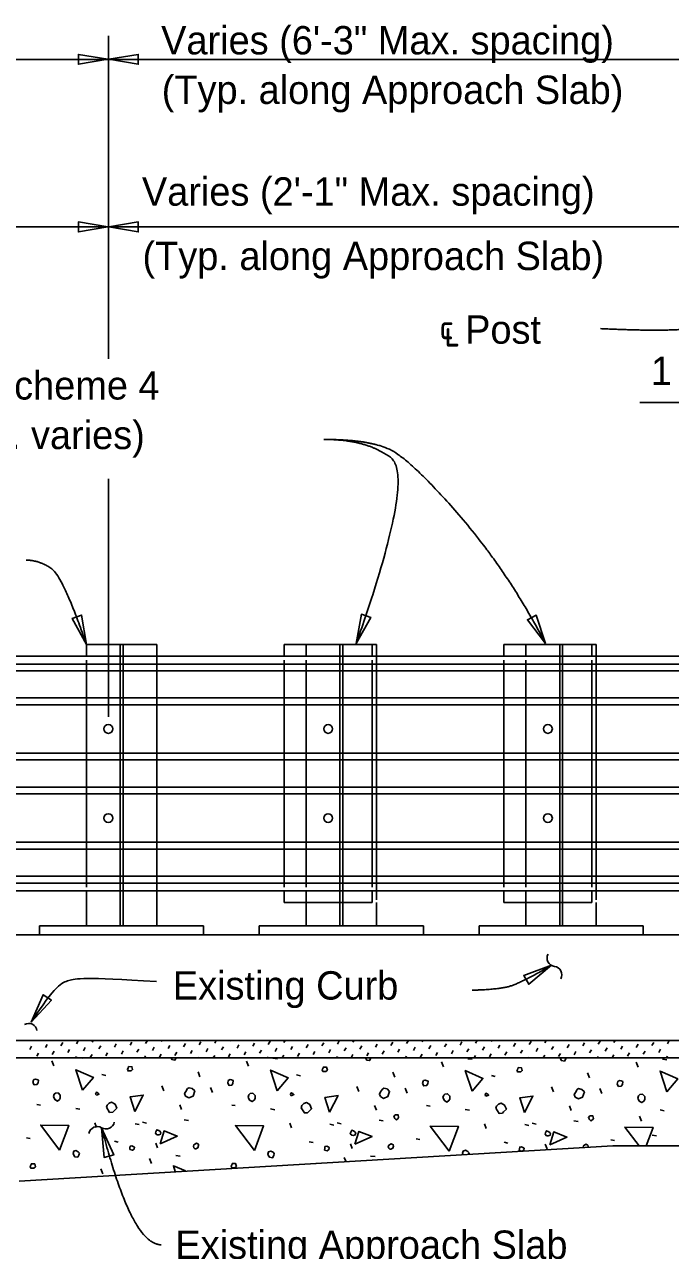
# Model space of a CAD drawing. Extents: x 0 to 41.1, y 0 to 25.9.
# Drawn here: x 8 to 12.6, y 5.22 to 13.93 of the extents above; entities that cross this region are included whole.
import ezdxf

# ---------------------------------------------------------------- set-up
doc = ezdxf.new("R2010")
doc.units = 0
for name, color, linetype in [('Dimension', 7, 'Continuous'), ('ExistSuperStruct', 7, 'Continuous'), ('Miscellaneous', 7, 'Continuous'), ('SteelMisc', 7, 'Continuous'), ('SteelMisc_h', 7, 'Continuous'), ('TextStructures', 7, 'Continuous')]:
    doc.layers.add(name, color=color, linetype=linetype)

msp = doc.modelspace()

# ---------------------------------------------------------------- linework, layer by layer
at = {"layer": 'Dimension'}
for p, q in [((8.5998, 11.5508), (8.5998, 13.8459)), ((18.0098, 13.6793), (2.1218, 13.6793)), ((17.9296, 12.4884), (2.1218, 12.4884)), ((16.1241, 11.2414), (12.3777, 11.2414)), ((8.5998, 9.0073), (8.5998, 10.6982))]:
    msp.add_line(p, q, dxfattribs=at)
for points in [[(8.5954, 13.6795), (8.3872, 13.6442), (8.3872, 13.7148)], [(8.6042, 13.6795), (8.8124, 13.6442), (8.8124, 13.7148)], [(8.5954, 12.4886), (8.3872, 12.4533), (8.3872, 12.5239)], [(8.6042, 12.4886), (8.8124, 12.4533), (8.8124, 12.5239)], [(8.4436, 9.5225), (8.4094, 9.7309), (8.3427, 9.708)], [(10.3626, 9.5296), (10.465, 9.7144), (10.3985, 9.7378)], [(11.7067, 9.5296), (11.642, 9.7307), (11.5794, 9.6982)], [(11.7511, 7.2434), (11.5884, 7.1087), (11.5531, 7.1698)], [(8.0517, 6.8399), (8.1359, 7.0336), (8.195, 6.9951)], [(8.5523, 6.0893), (8.5694, 5.8788), (8.6378, 5.8962)]]:
    msp.add_lwpolyline(points, close=True, dxfattribs=at)
for centre, start, end in [((11.7777, 7.2949), 151.52667, 263.25389), ((11.7637, 7.1765), 331.52667, 83.25389), ((8.0333, 6.7707), 7.95358, 119.6808), ((8.5209, 6.0382), 58.43842, 170.16564), ((8.5833, 6.1398), 238.43842, 350.16564)]:
    msp.add_arc(centre, 0.0596, start, end, dxfattribs=at)
for points, degree in [([(12.0979, 11.7665), (12.4051, 11.7514), (12.8084, 11.7632), (13.1866, 11.8516)], 2), ([(10.1319, 10.9791), (10.4429, 10.9791), (10.7789, 10.7133), (10.3626, 9.5296)], 2), ([(10.1319, 10.9791), (10.4429, 10.9791), (10.7438, 10.8437), (11.4409, 10.0412), (11.7067, 9.5296)], 2), ([(8.0155, 10.1215), (8.1146, 10.1215), (8.2813, 9.9961), (8.4436, 9.5225)], 2), ([(11.1859, 7.0665), (11.3674, 7.0712), (11.5265, 7.1137), (11.7511, 7.2435)], 2), ([(8.9418, 7.1274), (8.4203, 7.1612), (8.3169, 7.139), (8.2229, 7.1024), (8.0518, 6.8399)], 3), ([(8.5528, 6.0892), (8.764, 5.258), (8.9753, 5.258)], 2)]:
    msp.add_open_spline(points, degree=degree, dxfattribs=at)
at = {"layer": 'ExistSuperStruct'}
for p, q in [((6.9655, 7.4599), (14.9126, 7.4599)), ((17.3289, 6.71), (6.9655, 6.71)), ((6.9655, 6.585), (17.3289, 6.585)), ((12.1854, 5.9599), (7.9654, 5.7099)), ((17.3289, 5.9599), (12.1854, 5.9599))]:
    msp.add_line(p, q, dxfattribs=at)
at = {"layer": 'Miscellaneous'}
for p, q in [((9.8498, 9.5225), (10.4748, 9.5225)), ((9.8498, 9.5225), (9.8498, 9.4391)), ((10.4748, 9.5225), (10.4748, 9.4391)), ((11.4123, 9.5225), (12.0373, 9.5225)), ((11.4123, 9.5225), (11.4123, 9.4391)), ((12.0373, 9.5225), (12.0373, 9.4391)), ((9.8498, 9.4106), (9.8498, 7.7987)), ((10.4748, 9.4106), (10.4748, 7.7987)), ((11.4123, 9.4106), (11.4123, 7.7987)), ((12.0373, 9.4106), (12.0373, 7.7987)), ((9.8498, 7.6891), (9.8498, 7.7725)), ((10.4748, 7.6891), (10.4748, 7.7725)), ((11.4123, 7.6891), (11.4123, 7.7725)), ((12.0373, 7.6891), (12.0373, 7.7725)), ((9.8498, 7.6891), (10.4748, 7.6891)), ((11.4123, 7.6891), (12.0373, 7.6891)), ((8.1032, 6.7077), (8.1046, 6.71)), ((8.3733, 6.6848), (8.3863, 6.7072)), ((8.484, 6.6977), (8.4911, 6.71)), ((8.8647, 6.6878), (8.8776, 6.71)), ((8.9753, 6.7008), (8.9807, 6.71)), ((9.3561, 6.6908), (9.3672, 6.71)), ((9.4667, 6.7038), (9.4703, 6.71)), ((9.8474, 6.6938), (9.8568, 6.71)), ((9.9581, 6.7068), (9.9599, 6.71)), ((10.3388, 6.6969), (10.3464, 6.71)), ((10.4494, 6.7098), (10.4495, 6.71)), ((10.7195, 6.6869), (10.7325, 6.7093)), ((10.8302, 6.6999), (10.836, 6.71)), ((11.2109, 6.6899), (11.2225, 6.71)), ((11.3215, 6.7029), (11.3257, 6.71)), ((11.7023, 6.693), (11.7121, 6.71)), ((11.8129, 6.7059), (11.8153, 6.71)), ((12.1936, 6.696), (12.2018, 6.71)), ((12.3043, 6.7089), (12.3049, 6.71)), ((12.5744, 6.686), (12.5873, 6.7084)), ((8.0414, 6.6459), (8.0544, 6.6683)), ((8.0903, 6.597), (8.1032, 6.6194)), ((8.1521, 6.6588), (8.165, 6.6812)), ((8.2009, 6.61), (8.2139, 6.6324)), ((8.2627, 6.6718), (8.2757, 6.6942)), ((8.3115, 6.623), (8.3245, 6.6454)), ((8.4222, 6.6359), (8.4351, 6.6583)), ((8.5328, 6.6489), (8.5458, 6.6713)), ((8.5816, 6.6001), (8.5946, 6.6225)), ((8.6434, 6.6619), (8.6564, 6.6843)), ((8.6923, 6.613), (8.7052, 6.6354)), ((8.7541, 6.6748), (8.767, 6.6972)), ((8.8029, 6.626), (8.8159, 6.6484)), ((8.9135, 6.639), (8.9265, 6.6614)), ((9.0242, 6.6519), (9.0371, 6.6743)), ((9.073, 6.6031), (9.086, 6.6255)), ((9.1348, 6.6649), (9.1478, 6.6873)), ((9.1836, 6.6161), (9.1966, 6.6384)), ((9.2454, 6.6779), (9.2584, 6.7002)), ((9.2943, 6.629), (9.3072, 6.6514)), ((9.4049, 6.642), (9.4179, 6.6644)), ((9.5155, 6.6549), (9.5285, 6.6773)), ((9.5644, 6.6061), (9.5773, 6.6285)), ((9.6262, 6.6679), (9.6391, 6.6903)), ((9.675, 6.6191), (9.688, 6.6415)), ((9.7368, 6.6809), (9.7498, 6.7033)), ((9.7856, 6.632), (9.7986, 6.6544)), ((9.8963, 6.645), (9.9092, 6.6674)), ((10.0069, 6.658), (10.0199, 6.6804)), ((10.0557, 6.6091), (10.0687, 6.6315)), ((10.1175, 6.6709), (10.1305, 6.6933)), ((10.1664, 6.6221), (10.1793, 6.6445)), ((10.2282, 6.6839), (10.2411, 6.7063)), ((10.277, 6.6351), (10.29, 6.6574)), ((10.3876, 6.648), (10.4006, 6.6704)), ((10.4365, 6.5992), (10.4494, 6.6216)), ((10.4983, 6.661), (10.5112, 6.6834)), ((10.5471, 6.6121), (10.5601, 6.6345)), ((10.6089, 6.6739), (10.6219, 6.6963)), ((10.6577, 6.6251), (10.6707, 6.6475)), ((10.7684, 6.6381), (10.7813, 6.6605)), ((10.879, 6.651), (10.892, 6.6734)), ((10.9278, 6.6022), (10.9408, 6.6246)), ((10.9896, 6.664), (11.0026, 6.6864)), ((11.0385, 6.6152), (11.0514, 6.6376)), ((11.1003, 6.677), (11.1132, 6.6994)), ((11.1491, 6.6281), (11.1621, 6.6505)), ((11.2597, 6.6411), (11.2727, 6.6635)), ((11.3704, 6.6541), (11.3833, 6.6765)), ((11.4192, 6.6052), (11.4322, 6.6276)), ((11.481, 6.667), (11.494, 6.6894)), ((11.5298, 6.6182), (11.5428, 6.6406)), ((11.5916, 6.68), (11.6046, 6.7024)), ((11.6405, 6.6312), (11.6534, 6.6535)), ((11.7511, 6.6441), (11.7641, 6.6665)), ((11.8617, 6.6571), (11.8747, 6.6795)), ((11.9106, 6.6082), (11.9235, 6.6306)), ((11.9724, 6.67), (11.9853, 6.6924)), ((12.0212, 6.6212), (12.0342, 6.6436)), ((12.083, 6.683), (12.0959, 6.7054)), ((12.1318, 6.6342), (12.1448, 6.6566)), ((12.2425, 6.6471), (12.2554, 6.6695)), ((12.2913, 6.5983), (12.3043, 6.6207)), ((12.3531, 6.6601), (12.366, 6.6825)), ((12.4019, 6.6113), (12.4149, 6.6337)), ((12.4637, 6.6731), (12.4767, 6.6955)), ((12.5126, 6.6242), (12.5255, 6.6466)), ((8.2125, 6.5301), (8.1983, 6.5655)), ((8.3666, 6.585), (8.3733, 6.5965)), ((8.395, 6.585), (8.4169, 6.5825)), ((8.471, 6.5871), (8.484, 6.6095)), ((8.7531, 6.585), (8.7541, 6.5866)), ((8.8562, 6.585), (8.8647, 6.5996)), ((8.9624, 6.5901), (8.9753, 6.6125)), ((9.2427, 6.585), (9.2454, 6.5896)), ((9.3459, 6.585), (9.3561, 6.6026)), ((9.4537, 6.5931), (9.4667, 6.6155)), ((9.5972, 6.5266), (9.583, 6.5619)), ((9.7324, 6.585), (9.7368, 6.5926)), ((9.7698, 6.5825), (9.8016, 6.579)), ((9.8355, 6.585), (9.8474, 6.6056)), ((9.9451, 6.5962), (9.9581, 6.6186)), ((10.222, 6.585), (10.2282, 6.5957)), ((10.3258, 6.5862), (10.3388, 6.6086)), ((10.6085, 6.585), (10.6089, 6.5857)), ((10.7116, 6.585), (10.7195, 6.5987)), ((10.8172, 6.5892), (10.8302, 6.6116)), ((10.9818, 6.5231), (10.9677, 6.5584)), ((11.0981, 6.585), (11.1003, 6.5887)), ((11.1545, 6.579), (11.1863, 6.5755)), ((11.2012, 6.585), (11.2109, 6.6017)), ((11.3086, 6.5923), (11.3215, 6.6147)), ((11.5877, 6.585), (11.5916, 6.5917)), ((11.6908, 6.585), (11.7023, 6.6047)), ((11.7999, 6.5953), (11.8129, 6.6177)), ((12.0773, 6.585), (12.083, 6.5948)), ((12.1807, 6.5853), (12.1936, 6.6077)), ((12.3665, 6.5195), (12.3524, 6.5549)), ((12.5391, 6.5755), (12.571, 6.5719)), ((12.5669, 6.585), (12.5744, 6.5978)), ((8.553, 6.4676), (8.5813, 6.4606)), ((9.2513, 6.4517), (9.2372, 6.4871)), ((9.9377, 6.4641), (9.966, 6.457)), ((10.636, 6.4482), (10.6218, 6.4835)), ((11.3224, 6.4606), (11.3507, 6.4535)), ((12.0207, 6.4446), (12.0065, 6.48)), ((8.995, 6.351), (8.9808, 6.3863)), ((9.3391, 6.3392), (9.3249, 6.3746)), ((10.3797, 6.3474), (10.3655, 6.3828)), ((10.7237, 6.3357), (10.7096, 6.371)), ((11.7643, 6.3439), (11.7502, 6.3792)), ((12.1084, 6.3321), (12.0943, 6.3675)), ((8.0923, 6.2544), (8.117, 6.2508)), ((8.368, 6.2261), (8.3981, 6.2208)), ((9.1205, 6.2184), (9.1081, 6.252)), ((9.477, 6.2508), (9.5017, 6.2473)), ((9.7527, 6.2225), (9.7828, 6.2172)), ((10.5052, 6.2148), (10.4928, 6.2484)), ((10.8616, 6.2473), (10.8864, 6.2437)), ((11.1374, 6.219), (11.1675, 6.2137)), ((11.8898, 6.2113), (11.8775, 6.2449)), ((12.5221, 6.2155), (12.5521, 6.2102)), ((8.5165, 6.0917), (8.5042, 6.1253)), ((8.7905, 6.1182), (8.8188, 6.1112)), ((8.843, 6.1282), (8.8712, 6.1211)), ((9.1393, 6.1465), (9.1694, 6.1412)), ((9.9012, 6.0882), (9.8888, 6.1218)), ((10.1752, 6.1147), (10.2035, 6.1076)), ((10.2276, 6.1247), (10.2559, 6.1176)), ((10.524, 6.143), (10.554, 6.1377)), ((11.2859, 6.0846), (11.2735, 6.1182)), ((11.5599, 6.1112), (11.5882, 6.1041)), ((11.6123, 6.1211), (11.6406, 6.1141)), ((11.9087, 6.1394), (11.9387, 6.1341)), ((12.3904, 6.1363), (12.3763, 6.1717)), ((8.018, 6.0175), (8.0445, 6.0122)), ((10.7874, 6.0104), (10.8139, 6.0051)), ((12.4657, 6.0362), (12.4957, 6.0309)), ((8.6438, 5.9927), (8.6703, 5.9874)), ((8.949, 5.9456), (8.9366, 5.9792)), ((10.0285, 5.9892), (10.055, 5.9839)), ((10.3337, 5.9421), (10.3213, 5.9757)), ((11.4132, 5.9857), (11.4397, 5.9803)), ((11.7184, 5.9385), (11.706, 5.9721)), ((12.1716, 6.0033), (12.1981, 5.998)), ((8.9066, 5.836), (8.8925, 5.8714)), ((9.0792, 5.892), (9.111, 5.8884)), ((10.2877, 5.8518), (10.2771, 5.8783)), ((10.4639, 5.8884), (10.4957, 5.8849)), ((8.5607, 5.7611), (8.5466, 5.7965))]:
    msp.add_line(p, q, dxfattribs=at)
for points in [[(9.0453, 6.585), (9.0515, 6.5737), (9.0728, 6.5702), (9.081, 6.585)], [(10.428, 6.585), (10.4362, 6.5702), (10.4574, 6.5666), (10.4663, 6.5825), (10.4669, 6.585)], [(11.8108, 6.585), (11.8121, 6.5825)], [(11.8121, 6.5825), (11.8209, 6.5666), (11.8421, 6.5631), (11.851, 6.579), (11.8524, 6.585)], [(8.4158, 6.3551), (8.368, 6.5018), (8.4936, 6.447), (8.4158, 6.3551)], [(8.7404, 6.4924), (8.7616, 6.4924), (8.7722, 6.503), (8.7669, 6.5224), (8.744, 6.5242), (8.7404, 6.5136), (8.7351, 6.5047), (8.7404, 6.4924), (8.7369, 6.4959)], [(9.8005, 6.3516), (9.7527, 6.4983), (9.8782, 6.4435), (9.8005, 6.3516)], [(10.1251, 6.4888), (10.1463, 6.4888), (10.1569, 6.4994), (10.1516, 6.5189), (10.1286, 6.5207), (10.1251, 6.5101), (10.1198, 6.5012), (10.1251, 6.4888), (10.1216, 6.4924)], [(11.1851, 6.348), (11.1374, 6.4948), (11.2629, 6.44), (11.1851, 6.348)], [(11.5098, 6.4853), (11.531, 6.4853), (11.5416, 6.4959), (11.5363, 6.5154), (11.5133, 6.5171), (11.5098, 6.5065), (11.5045, 6.4977), (11.5098, 6.4853), (11.5062, 6.4888)], [(12.5698, 6.3445), (12.5221, 6.4912), (12.6476, 6.4364), (12.5698, 6.3445)], [(8.064, 6.4099), (8.0728, 6.394), (8.0923, 6.3958), (8.1011, 6.4081), (8.1029, 6.4276), (8.0905, 6.4329), (8.0817, 6.4347), (8.0711, 6.4311), (8.0675, 6.4276), (8.064, 6.4099)], [(9.1488, 6.3138), (9.1718, 6.3015), (9.2018, 6.3138), (9.2142, 6.351), (9.1965, 6.3686), (9.1735, 6.3739), (9.1629, 6.3669), (9.1505, 6.3474), (9.1417, 6.3315), (9.1488, 6.3138)], [(9.4487, 6.4064), (9.4575, 6.3905), (9.477, 6.3922), (9.4858, 6.4046), (9.4876, 6.4241), (9.4752, 6.4294), (9.4663, 6.4311), (9.4557, 6.4276), (9.4522, 6.4241), (9.4487, 6.4064)], [(10.5335, 6.3103), (10.5564, 6.2979), (10.5865, 6.3103), (10.5989, 6.3474), (10.5812, 6.3651), (10.5582, 6.3704), (10.5476, 6.3633), (10.5352, 6.3439), (10.5264, 6.328), (10.5335, 6.3103)], [(10.8333, 6.4028), (10.8422, 6.3869), (10.8616, 6.3887), (10.8705, 6.4011), (10.8722, 6.4205), (10.8599, 6.4258), (10.851, 6.4276), (10.8404, 6.4241), (10.8369, 6.4205), (10.8333, 6.4028)], [(11.9181, 6.3068), (11.9411, 6.2944), (11.9712, 6.3068), (11.9835, 6.3439), (11.9659, 6.3616), (11.9429, 6.3669), (11.9323, 6.3598), (11.9199, 6.3403), (11.9111, 6.3244), (11.9181, 6.3068)], [(12.218, 6.3993), (12.2269, 6.3834), (12.2463, 6.3852), (12.2551, 6.3975), (12.2569, 6.417), (12.2445, 6.4223), (12.2357, 6.4241), (12.2251, 6.4205), (12.2216, 6.417), (12.218, 6.3993)], [(8.209, 6.3109), (8.2196, 6.2897), (8.2372, 6.2791), (8.2514, 6.2897), (8.2584, 6.3003), (8.2584, 6.3215), (8.2425, 6.3374), (8.2231, 6.3357), (8.2143, 6.3268), (8.209, 6.3109)], [(8.5148, 6.3198), (8.5342, 6.3286), (8.5271, 6.3357), (8.5148, 6.341), (8.5095, 6.3286), (8.5148, 6.3198)], [(8.5855, 6.2349), (8.6085, 6.1978), (8.6314, 6.1996), (8.6403, 6.2084), (8.6597, 6.2278), (8.6474, 6.2579), (8.6226, 6.272), (8.6049, 6.265), (8.5908, 6.2508), (8.5855, 6.2349)], [(8.7882, 6.2042), (8.7546, 6.3085), (8.8483, 6.3209), (8.7882, 6.2042)], [(9.5936, 6.3074), (9.6042, 6.2862), (9.6219, 6.2756), (9.6361, 6.2862), (9.6431, 6.2968), (9.6431, 6.318), (9.6272, 6.3339), (9.6078, 6.3321), (9.5989, 6.3233), (9.5936, 6.3074)], [(9.8995, 6.3162), (9.9189, 6.3251), (9.9118, 6.3321), (9.8995, 6.3374), (9.8941, 6.3251), (9.8995, 6.3162)], [(10.1728, 6.2007), (10.1392, 6.305), (10.2329, 6.3174), (10.1728, 6.2007)], [(10.9783, 6.3039), (10.9889, 6.2826), (11.0066, 6.272), (11.0207, 6.2826), (11.0278, 6.2932), (11.0278, 6.3145), (11.0119, 6.3304), (10.9924, 6.3286), (10.9836, 6.3198), (10.9783, 6.3039)], [(11.2841, 6.3127), (11.3036, 6.3215), (11.2965, 6.3286), (11.2841, 6.3339), (11.2788, 6.3215), (11.2841, 6.3127)], [(11.5575, 6.1972), (11.5239, 6.3015), (11.6176, 6.3138), (11.5575, 6.1972)], [(12.363, 6.3003), (12.3736, 6.2791), (12.3913, 6.2685), (12.4054, 6.2791), (12.4125, 6.2897), (12.4125, 6.3109), (12.3966, 6.3268), (12.3771, 6.3251), (12.3683, 6.3162), (12.363, 6.3003)], [(9.9702, 6.2314), (9.9931, 6.1942), (10.0161, 6.196), (10.025, 6.2049), (10.0444, 6.2243), (10.032, 6.2544), (10.0073, 6.2685), (9.9896, 6.2614), (9.9755, 6.2473), (9.9702, 6.2314)], [(11.3548, 6.2278), (11.3778, 6.1907), (11.4008, 6.1925), (11.4096, 6.2013), (11.4291, 6.2208), (11.4167, 6.2508), (11.392, 6.265), (11.3743, 6.2579), (11.3601, 6.2437), (11.3548, 6.2278)], [(8.2531, 5.9309), (8.1188, 6.1076), (8.3186, 6.1059), (8.2531, 5.9309)], [(9.6378, 5.9273), (9.5035, 6.1041), (9.7032, 6.1023), (9.6378, 5.9273)], [(10.6354, 6.1554), (10.646, 6.1448), (10.6566, 6.1518), (10.6636, 6.1624), (10.6601, 6.1801), (10.6513, 6.1819), (10.6389, 6.1801), (10.6283, 6.1695), (10.6354, 6.1554)], [(11.0225, 5.9238), (10.8881, 6.1006), (11.0879, 6.0988), (11.0225, 5.9238)], [(12.0195, 6.1483), (12.0301, 6.1377), (12.0408, 6.1448), (12.0478, 6.1554), (12.0443, 6.173), (12.0354, 6.1748), (12.0231, 6.173), (12.0125, 6.1624), (12.0195, 6.1483)], [(8.9455, 6.0398), (8.9579, 6.0381), (8.9702, 6.0434), (8.9738, 6.054), (8.9685, 6.0628), (8.9579, 6.0699), (8.9455, 6.0752), (8.9384, 6.061), (8.9349, 6.0504), (8.9455, 6.0398)], [(8.9678, 5.975), (8.9961, 6.067), (9.0898, 6.0298), (8.9678, 5.975)], [(10.3302, 6.0363), (10.3425, 6.0345), (10.3549, 6.0398), (10.3584, 6.0504), (10.3531, 6.0593), (10.3425, 6.0663), (10.3302, 6.0716), (10.3231, 6.0575), (10.3196, 6.0469), (10.3302, 6.0363)], [(10.3525, 5.9715), (10.3808, 6.0634), (10.4745, 6.0263), (10.3525, 5.9715)], [(11.7148, 6.0328), (11.7272, 6.031), (11.7396, 6.0363), (11.7431, 6.0469), (11.7378, 6.0557), (11.7272, 6.0628), (11.7148, 6.0681), (11.7078, 6.054), (11.7042, 6.0434), (11.7148, 6.0328)], [(11.7372, 5.968), (11.7655, 6.0599), (11.8592, 6.0228), (11.7372, 5.968)], [(12.3738, 5.9599), (12.2723, 6.0935), (12.4721, 6.0917), (12.4228, 5.9599)], [(8.3521, 5.899), (8.361, 5.8831), (8.3822, 5.8796), (8.391, 5.8955), (8.3946, 5.9096), (8.3857, 5.9185), (8.3698, 5.9273), (8.3539, 5.922), (8.3486, 5.9061), (8.3521, 5.899)], [(8.7517, 5.9344), (8.7711, 5.9291), (8.7835, 5.9379), (8.7852, 5.9503), (8.7817, 5.9538), (8.7676, 5.9609), (8.7552, 5.9591), (8.7534, 5.9468), (8.7517, 5.9344)], [(9.2153, 5.9397), (9.2224, 5.9397), (9.2365, 5.9468), (9.2418, 5.9627), (9.2401, 5.9715), (9.2259, 5.9786), (9.2083, 5.968), (9.2047, 5.9574), (9.2083, 5.9468), (9.2153, 5.9397)], [(9.7368, 5.8955), (9.7457, 5.8796), (9.7669, 5.8761), (9.7757, 5.892), (9.7792, 5.9061), (9.7704, 5.9149), (9.7545, 5.9238), (9.7386, 5.9185), (9.7333, 5.9026), (9.7368, 5.8955)], [(10.1363, 5.9309), (10.1558, 5.9255), (10.1682, 5.9344), (10.1699, 5.9468), (10.1664, 5.9503), (10.1522, 5.9574), (10.1399, 5.9556), (10.1381, 5.9432), (10.1363, 5.9309)], [(10.6, 5.9362), (10.6071, 5.9362), (10.6212, 5.9432), (10.6265, 5.9591), (10.6248, 5.968), (10.6106, 5.975), (10.5929, 5.9644), (10.5894, 5.9538), (10.5929, 5.9432), (10.6, 5.9362)], [(11.1623, 5.9047), (11.1639, 5.9113), (11.1551, 5.9202), (11.1392, 5.929), (11.1233, 5.9237), (11.118, 5.9078), (11.1208, 5.9021)], [(11.521, 5.9273), (11.5405, 5.922), (11.5528, 5.9309), (11.5546, 5.9432), (11.5511, 5.9468), (11.5369, 5.9538), (11.5245, 5.9521), (11.5228, 5.9397), (11.521, 5.9273)], [(12.009, 5.9489), (12.0112, 5.9556), (12.0094, 5.9644), (11.9953, 5.9715), (11.9776, 5.9609), (11.9741, 5.9503), (11.9752, 5.9468)], [(9.4783, 5.8041), (9.4995, 5.8041), (9.5101, 5.8147), (9.5048, 5.8341), (9.4818, 5.8359), (9.4783, 5.8253), (9.473, 5.8165), (9.4783, 5.8041), (9.4748, 5.8076)], [(8.0499, 5.8018), (8.0711, 5.8018), (8.0817, 5.8124), (8.0764, 5.8319), (8.0534, 5.8336), (8.0499, 5.823), (8.0445, 5.8142), (8.0499, 5.8018), (8.0463, 5.8053)], [(9.0759, 5.7777), (9.0622, 5.8198), (9.1484, 5.7822)]]:
    msp.add_lwpolyline(points, dxfattribs=at)
at = {"layer": 'SteelMisc'}
for p, q in [((8.4436, 9.5225), (8.9436, 9.5225)), ((8.4436, 9.5225), (8.4436, 9.4391)), ((8.9436, 9.5225), (8.9436, 9.4391)), ((12.7651, 9.4391), (0.6692, 9.4391)), ((0.6692, 9.3835), (12.7651, 9.3835)), ((0.6692, 9.3353), (12.7651, 9.3353)), ((0.6692, 9.1425), (12.7651, 9.1425)), ((0.6692, 9.0943), (12.7651, 9.0943)), ((0.6692, 8.7503), (12.7651, 8.7503)), ((0.6692, 8.7021), (12.7651, 8.7021)), ((0.6692, 8.5093), (12.7651, 8.5093)), ((0.6692, 8.4611), (12.7651, 8.4611)), ((0.6692, 8.1172), (12.7651, 8.1172)), ((0.6692, 8.069), (12.7651, 8.069)), ((0.6692, 7.8761), (12.7651, 7.8761)), ((0.6692, 7.8279), (12.7651, 7.8279)), ((12.7651, 7.7724), (0.6692, 7.7724)), ((8.4436, 7.7725), (8.4436, 7.5225)), ((8.9436, 7.7724), (8.9436, 7.5225)), ((8.1102, 7.5225), (9.2769, 7.5225)), ((8.1102, 7.46), (8.1102, 7.5225)), ((8.4436, 7.5225), (8.9436, 7.5225)), ((9.2769, 7.5225), (9.2769, 7.46)), ((8.1102, 7.46), (9.2769, 7.46))]:
    msp.add_line(p, q, dxfattribs=at)
for centre in [(8.5998, 8.9224), (8.5998, 8.2892)]:
    msp.add_circle(centre, 0.0312, dxfattribs=at)
at = {"layer": 'SteelMisc_h'}
for p, q in [((8.6832, 7.5225), (8.6832, 9.5225)), ((8.704, 7.5225), (8.704, 9.5225)), ((10.0061, 9.5225), (10.5061, 9.5225)), ((10.0061, 9.5225), (10.0061, 9.4391)), ((10.2457, 7.5225), (10.2457, 9.5225)), ((10.2665, 7.5225), (10.2665, 9.5225)), ((10.5061, 9.5225), (10.5061, 7.7094)), ((11.5686, 9.5225), (12.0686, 9.5225)), ((11.5686, 9.5225), (11.5686, 9.4391)), ((11.8082, 7.5225), (11.8082, 9.5225)), ((11.829, 7.5225), (11.829, 9.5225)), ((12.0686, 9.5225), (12.0686, 7.7094)), ((8.4436, 9.4106), (8.4436, 7.7987)), ((8.9436, 9.4391), (8.9436, 7.7724)), ((10.0061, 9.4106), (10.0061, 7.7987)), ((11.5686, 9.4106), (11.5686, 7.7987)), ((10.0061, 7.7725), (10.0061, 7.5225)), ((11.5686, 7.7725), (11.5686, 7.5225)), ((10.5061, 7.6891), (10.5061, 7.5225)), ((12.0686, 7.6891), (12.0686, 7.5225)), ((9.6727, 7.5225), (10.8394, 7.5225)), ((9.6727, 7.46), (9.6727, 7.5225)), ((10.0061, 7.5225), (10.5061, 7.5225)), ((10.8394, 7.5225), (10.8394, 7.46)), ((11.2352, 7.5225), (12.4019, 7.5225)), ((11.2352, 7.46), (11.2352, 7.5225)), ((11.5686, 7.5225), (12.0686, 7.5225)), ((12.4019, 7.5225), (12.4019, 7.46)), ((9.6727, 7.46), (10.8394, 7.46)), ((11.2352, 7.46), (12.4019, 7.46))]:
    msp.add_line(p, q, dxfattribs=at)
for centre in [(10.1623, 8.9224), (11.7248, 8.9224), (10.1623, 8.2892), (11.7248, 8.2892)]:
    msp.add_circle(centre, 0.0312, dxfattribs=at)

# ---------------------------------------------------------------- texts
at = {"layer": 'Dimension'}
for s, p in [('Varies (6\'-3" Max. spacing)', (8.9751, 13.7145)), ('(Typ. along Approach Slab)', (8.9793, 13.3625)), ('Varies (2\'-1" Max. spacing)', (8.8384, 12.6398)), ('(Typ. along Approach Slab)', (8.8426, 12.1822)), ('Additional Posts required for Scheme 4 ', (4.2887, 11.2625)), ('(shown dashed, number Reqd. varies)', (4.2887, 10.9105))]:
    msp.add_text(s, height=0.2016, dxfattribs=at).set_placement(p)
at = {"layer": 'TextStructures'}
for s, p in [('℄ Post', (10.952, 11.6593)), ('1', (12.4568, 11.3663)), ('Existing Curb', (9.058, 6.9996)), ('Existing Approach Slab', (9.0763, 5.1574))]:
    msp.add_text(s, height=0.2016, dxfattribs=at).set_placement(p)

doc.saveas('drawing.dxf')
